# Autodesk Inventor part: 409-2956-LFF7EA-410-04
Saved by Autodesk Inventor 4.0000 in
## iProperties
Created: 2010-06
Part Number: 409-2956-LFF7EA-410-04
Cost Center: 0 lbmass
Material: A304 STAINLESS STEEL
Document SubType Name: Sheet Metal
Designer: S. Boerckel
Authority: 0 in^3
Mass: 155.751 g
Surface Area: 164.242 cm^2
Volume: 19.2761 cm^3
Density: 8.08 g/cm^3
Flat Pattern Width: 10.16 cm
Flat Pattern Length: 10.16 cm
Flat Pattern Area: 103.226 cm^2
Sheet Metal Rule: 12Ga
Sheet Metal Width: 4.0000 in
Sheet Metal Length: 16.0000 in^2
Description: STRAINER 186Ga SHIM
User Status: BURN
SaveDate: 2008-01-15
SaveTime: 10:24
FileName: Sheet Metal
Wide: =<Flat Pattern Width>cm
Length: =<Flat Pattern Length>cm
Thickness: 0.1046 in
SMR: =<Sheet Metal Rule> - <Material>
Author: S. Boerckel
Revision Number: 0
Title: STRAINER 18Ga SHIM
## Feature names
1. Plate1
2. Cut1
